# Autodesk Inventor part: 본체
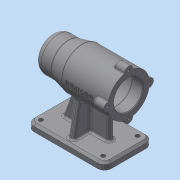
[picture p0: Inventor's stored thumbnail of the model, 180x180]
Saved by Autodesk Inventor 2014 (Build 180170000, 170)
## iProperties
Created: 2019-07
Part Number: 본체
Material: Generic
Document SubType Name: Modeling
Designer: mm
Density: 1 g/cm^3
Appearance: Default
Author: mm
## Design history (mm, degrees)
sketch "스케치1"
  geometry: L1 (-56, 35)-(56, 35); L2 (56, 35)-(56, -35); L3 (56, -35)-(-56, -35); L4 (-56, -35)-(-56, 35); L5 (-56, 35)-(56, -35); L6 (56, 35)-(-56, -35); 1 further point
  constraints: 12 end point, 2 midpoint, 2 parallel, 1 horizontal, 1 perpendicular
  dimensions: "d0" = 112 distance between parallel lines of L2 L4; "d1" = 70 distance between parallel lines of L3 L1
extrude "돌출1" new body sketch "스케치1" distance "d2" = 10; taper "d3" = 0 deg
sketch "스케치2"
  geometry: L1 (56, 80)-(-56, 80); L2 (56, 80)-(56, 105); L3 (56, 105)-(31, 105); L4 (31, 105)-(11, 110); L5 (11, 110)-(-56, 110); L6 (-56, 110)-(-56, 80); L7 (-56, 0)-(56, 0) reference; 1 further point
  constraints: 12 end point, 2 parallel, 2 perpendicular, 1 horizontal, 1 vertical alignment
  dimensions: "d4" = 50 diameter of L3 L1; "d5" = 60 diameter of L5 L1; "d6" = 25 distance from line of L3.end L2; "d7" = 45 distance from line of L4.end L2; "d8" = 80 distance from line of L7 L1.start; "d9" = 112 distance between parallel lines of L2 L6
revolve "회전1" sketch "스케치2" stored, may be unused: angle "d10" = 90 deg
sketch "스케치3"
  geometry: L1 (15.657, 80)-(-15.657, 80); L2 (15.657, 80)-(28, 10); L3 (-15.657, 80)-(-28, 10); L4 (28, 10)-(-28, 10); L5 (35, 0)-(-35, 0) reference; L6 (-35, 10)-(35, 10) reference; L7 (35, 0)-(35, 10) reference; 3 further points
  constraints: 8 end point, 2 midpoint, 1 collinear, 1 horizontal, 1 parallel, 1 vertical alignment
  dimensions: "d11" = 80 distance between parallel lines of L5 L1; "d12" = 100 deg angle of L2 L6; "d13" = 100 deg angle of L6 L3; "d14" = 7 distance from line of L2.end L7
extrude "돌출2" join sketch "스케치3" stored distance "d15" = 8; taper "d16" = 0 deg
sketch "스케치4"
  geometry: L1 (36, 10)-(10.522, 80); L2 (10.522, 80)-(-31, 80); L3 (-31, 80)-(-31, 10); L4 (36, 10)-(-31, 10); L5 (-56, 0)-(-56, 10) reference; L6 (56, 0)-(56, 10) reference; L7 (-56, 10)-(56, 10) reference; L8 (56, 0)-(-56, 0) reference; 1 further point
  constraints: 8 end point, 2 perpendicular, 1 collinear, 1 horizontal
  dimensions: "d17" = 25 distance from line of L3.end L5; "d18" = 20 distance from line of L1.start L6; "d19" = 110 deg angle of L1 L7; "d20" = 80 distance between parallel lines of L2 L8
extrude "돌출3" join sketch "스케치4" stored distance "d21" = 8; taper "d22" = 0 deg
sketch "스케치5"
  geometry: L1 (-56, 80)-(51, 80); L2 (51, 80)-(51, 90.5); L3 (51, 90.5)-(48, 90.5); L4 (48, 90.5)-(48, 96); L5 (48, 96)-(44, 96); L6 (44, 96)-(44, 97.5); L7 (44, 97.5)-(26, 97.5); L8 (26, 97.5)-(26, 101); L9 (26, 101)-(14, 101); L10 (14, 101)-(14, 104); L11 (14, 104)-(-40, 104); L12 (-40, 104)-(-40, 101); L13 (-40, 101)-(-56, 101); L14 (-56, 101)-(-56, 80); L15 (-56, 50)-(-56, 110) reference; L16 (56, 0)-(-56, 0) reference; 1 further point
  constraints: 28 end point, 10 parallel, 3 perpendicular, 1 collinear, 1 horizontal
  dimensions: "d23" = 48 diameter of L11 L1; "d24" = 42 diameter of L9 L1; "d25" = 42 diameter of L13 L1; "d26" = 35 diameter of L7 L1; "d27" = 32 diameter of L5 L1; "d28" = 21 diameter of L3 L1; "d29" = 3 distance between parallel lines of L4 L2; "d30" = 4 distance between parallel lines of L6 L4; "d31" = 18 distance between parallel lines of L8 L6; "d32" = 11.99959 distance between parallel lines of L10 L8; "d33" = 80 distance between parallel lines of L16 L1; "d34" = 16 distance between parallel lines of L12 L14; "d35" = 54 distance between parallel lines of L12 L10
revolve "회전2" sketch "스케치5" stored, may be unused: angle "d36" = 90 deg
sketch "스케치6"
  geometry: C1 r 21 at (0, 0) reference; C2 r 30 at (0, 0); C3 r 6 at (-30, 0); 2 further points
  constraints: 2 centre point, 2 horizontal alignment, 1 coincident, 1 other
  dimensions: "d37" = 60 diameter of C2; "d38" = 6 radius of C3
extrude "돌출4" join sketch "스케치6" distance "d39" = 16; taper "d40" = 0 deg
sketch "스케치7"
  geometry: A1 r 6 centre (0, 0) between (0.6, 5.97) and (0.6, -5.97) reference; 2 further points
  constraints: 1 coincident
hole "구멍1" sketch "스케치7" at (0, 0) diameter "d44" = 3.242; stored, may be unused: countersink angle "d48" = 90 deg, drill point angle "d50" = 118 deg; dims "d45" = 8, "d46" = 4, "d47" = 2, "d49" = 11
fillet "모깎기1" dims "d54" = 10
fillet "모깎기2" dims "d55" = 10
hole "구멍2" diameter "d58" = 6; stored, may be unused: countersink angle "d62" = 90 deg, drill point angle "d64" = 118 deg; dims "d56" = 10, "d57" = 10, "d59" = 8, "d60" = 4, "d61" = 2, "d63" = 11
chamfer "모따기1" distance "d71" = 1; stored, may be unused: second distance "d72" = 2, angle "d73" = 45 deg
fillet "모깎기3" dims "d74" = 3
fillet "모깎기4" dims "d75" = 3
fillet "모깎기5" dims "d76" = 1
fillet "모깎기6" dims "d77" = 3
fillet "모깎기7" dims "d78" = 3
fillet "모깎기8" dims "d79" = 3
chamfer "모따기2" distance "d80" = 3; stored, may be unused: second distance "d81" = 2, angle "d82" = 45 deg
fillet "모깎기9" dims "d83" = 0.3
fillet "모깎기10" dims "d84" = 3
node "작업 평면1"
sketch "스케치8"
  geometry: L1 (-11, 85)-(39, 85); L2 (39, 85)-(39, 75); L3 (39, 75)-(-11, 75); L4 (-11, 75)-(-11, 85); L5 (-11, 80)-(39, 80); L6 (14, 85)-(14, 75); L7 (46, 0)-(-46, 0) reference; L8 (56, 109.226)-(56, 86.771) reference; 1 further point
  constraints: 4 end point, 4 midpoint, 2 other
  dimensions: "d86" = 50 distance between parallel lines of L2 L4; "d87" = 10 distance between parallel lines of L3 L1; "d88" = 80 distance between parallel lines of L5 L7; "d89" = 42 distance between parallel lines of L6 L8
feature "엠보싱1" sketch "스케치8" dims "d0" = 112, "d1" = 70, "d11" = 80, "d12" = 100 deg, "d13" = 100 deg, "d14" = 7, "d90" = 0.5, "d91" = 0
node "솔리드1"
pattern_circular "원형 패턴1" dims angle "d42" = 360 deg
pattern_circular "원형 패턴2" dims angle "d52" = 360 deg
pattern_linear "직사각형 패턴1" dims "d67" = 90
other parameters: "d85" = -35
